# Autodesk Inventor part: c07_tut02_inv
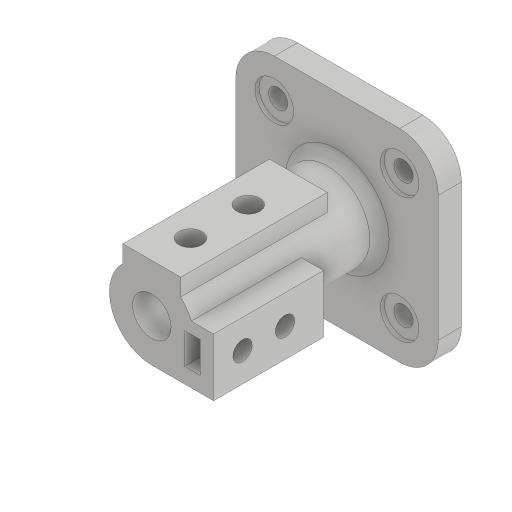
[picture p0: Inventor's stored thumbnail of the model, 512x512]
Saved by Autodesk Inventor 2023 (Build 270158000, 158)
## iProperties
Created: 2017-04
Part Number: c07_tut02_inv
Material: Generic
Document SubType Name: Modeling
Designer: CADCIM 00
Density: 1 g/cm^3
Appearance: Default
Author: CADCIM 00
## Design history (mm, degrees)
sketch "Sketch1"
  geometry: L1 (-32.5, -52.5)-(32.5, -52.5); L2 (52.5, -32.5)-(52.5, 32.5); L3 (32.5, 52.5)-(-32.5, 52.5); L4 (-52.5, 32.5)-(-52.5, -32.5); L5 (-52.5, -52.5)-(52.5, 52.5); L6 (52.5, -52.5)-(-52.5, 52.5); A1 r 20 centre (32.5, 32.5) between (52.5, 32.5) and (32.5, 52.5); A2 r 20 centre (-32.5, 32.5) between (-32.5, 52.5) and (-52.5, 32.5); A3 r 20 centre (-32.5, -32.5) between (-52.5, -32.5) and (-32.5, -52.5); A4 r 20 centre (32.5, -32.5) between (32.5, -52.5) and (52.5, -32.5); 1 further point
  constraints: 12 end point, 8 point on circle, 8 point on line, 8 tangent, 4 centre point, 3 equal radius, 2 midpoint, 2 parallel, 2 perpendicular, 1 horizontal
  dimensions: "d0" = 105 distance of L5.end L6.end; "d1" = 20 radius of A1
extrude "Extrusion1" new body sketch "Sketch1" distance "d2" = 12; taper "d3" = 0 deg
sketch "Sketch10"
  geometry: A1 r 20 centre (32.5, 32.5) between (52.5, 32.5) and (32.5, 52.5) reference; 1 further point
  constraints: 1 coincident
hole "Hole1" sketch "Sketch10" at (32.5, 32.5) diameter "d6" = 10; stored, may be unused: countersink angle "d10" = 90 deg, drill point angle "d12" = 118 deg; dims "d7" = 6, "d8" = 20, "d9" = 2, "d11" = 8
hole "Hole2" diameter "d15" = 10; stored, may be unused: countersink angle "d19" = 90 deg, drill point angle "d21" = 118 deg; dims "d13" = 10, "d14" = 10, "d16" = 6, "d17" = 20, "d18" = 2, "d20" = 8
hole "Hole3" diameter "d24" = 10; stored, may be unused: countersink angle "d28" = 90 deg, drill point angle "d30" = 118 deg; dims "d22" = 10, "d23" = 10, "d25" = 6, "d26" = 20, "d27" = 2, "d29" = 8
hole "Hole4" diameter "d33" = 10; stored, may be unused: countersink angle "d37" = 90 deg, drill point angle "d39" = 118 deg; dims "d31" = 10, "d32" = 10, "d34" = 6, "d35" = 20, "d36" = 2, "d38" = 8
sketch "Sketch2"
  geometry: C1 r 22 at (0, 0); 1 further point
  constraints: 1 centre point, 1 coincident
  dimensions: "d40" = 44 diameter of C1
extrude "Extrusion2" join sketch "Sketch2" distance "d41" = 96; taper "d42" = 0 deg
sketch "Sketch3"
  geometry: L1 (-15, 25)-(15, 25); L2 (15, 25)-(15, 16.093); L3 (-15, 16.093)-(-15, 25); L4 (0, 0)-(0, 59.776); A1 r 22 centre (0, 0) between (-15, 16.093) and (15, 16.093) reference; 1 further point
  constraints: 8 end point, 2 point on circle, 1 horizontal, 1 parallel, 1 perpendicular, 1 vertical, 1 other
  dimensions: "d43" = 30 distance between parallel lines of L2 L3; "d44" = 25 distance from line of L1 point (0, 0)
extrude "Extrusion3" join sketch "Sketch3" distance "d45" = 76; taper "d46" = 0 deg
sketch "Sketch4"
  geometry: L1 (32, 8)-(20.494, 8); L2 (32, -22)-(32, 8); L3 (0, 0)-(52.5, 0); L4 (52.5, -32.5)-(52.5, 32.5) reference; L5 (0, -22)-(32, -22); A1 r 22 centre (0, 0) between (-15, 16.093) and (15, 16.093) reference; 1 further point
  constraints: 8 end point, 3 horizontal, 2 point on circle, 1 midpoint, 1 tangent, 1 vertical
  dimensions: "d47" = 30 distance of L2.start L1.start; "d48" = 32 distance from line of point (0, 0) L2
extrude "Extrusion4" join sketch "Sketch4" distance "d49" = 57; taper "d50" = 0 deg
sketch "Sketch6"
  geometry: L1 (25, 2)-(17, 2); L2 (17, 2)-(17, -14); L3 (17, -14)-(25, -14); L4 (25, -14)-(25, 2); L5 (0, 0)-(52.778, 0)
  constraints: 10 end point, 2 horizontal, 2 parallel, 1 perpendicular
  dimensions: "d51" = 8 distance of L1.start L1.end; "d52" = 16 distance of L3.end L1.start; "d53" = 25 distance from line of L4 L5.start; "d72" = 2 distance between parallel lines of L1 L5
extrude "Extrusion5" cut sketch "Sketch6" distance "d54" = 50; taper "d55" = 0 deg
sketch "Sketch7"
  geometry: C1 r 10 at (0, 0); 1 further point
  constraints: 1 centre point, 1 coincident
  dimensions: "d56" = 20 diameter of C1
extrude "Extrusion6" cut sketch "Sketch7" stored distance "d57" = 57; taper "d58" = 0 deg
sketch "Sketch8"
  geometry: L1 (30, 0)-(0, 0) reference; L2 (0, 0)-(0, 76) reference; C1 r 6 at (15, 50); C2 r 6 at (15, 20); 1 further point
  constraints: 2 centre point, 1 equal radius, 1 vertical alignment
  dimensions: "d59" = 30 distance of C2.centre C1.centre; "d60" = 12 diameter of C1; "d61" = 20 distance from line of L1 C2.centre; "d62" = 15 distance from line of L2 C2.centre
extrude "Extrusion7" cut sketch "Sketch8" stored distance "d63" = 57; taper "d64" = 0 deg
sketch "Sketch9"
  geometry: L1 (0, 0)-(0, 57) reference; L2 (30, 0)-(0, 0) reference; C1 r 5 at (15, 15); C2 r 5 at (15, 37); 1 further point
  constraints: 2 centre point, 1 equal radius, 1 vertical alignment
  dimensions: "d65" = 10 diameter of C1; "d66" = 22 distance of C2.centre C1.centre; "d67" = 15 distance from line of L1 C1.centre; "d68" = 15 distance from line of L2 C1.centre
extrude "Extrusion8" cut sketch "Sketch9" stored distance "d69" = 57; taper "d70" = 0 deg
fillet "Fillet1" dims "d71" = 5
body "Solid1"
